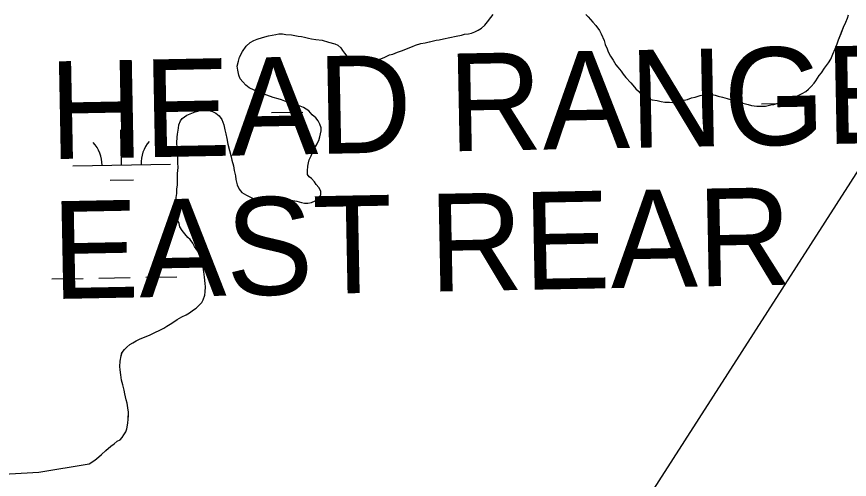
# Model space of a CAD drawing. Extents: x 3925854 to 3964121, y 224593 to 250589.
# Drawn here: x 3944344 to 3945197, y 233989 to 234463 of the extents above; entities that cross this region are included whole.
import ezdxf

# ---------------------------------------------------------------- set-up
doc = ezdxf.new("R2010")
doc.units = 0
for name, color, linetype in [('V-CHAN-NAID', 7, 'Continuous'), ('V-TOPO-SHOR', 7, 'Continuous'), ('V-UTIL-LINE', 7, 'Continuous'), ('V-WETL-SWMP', 7, 'Continuous')]:
    doc.layers.add(name, color=color, linetype=linetype)

msp = doc.modelspace()

# ---------------------------------------------------------------- linework, layer by layer
at = {"layer": 'V-TOPO-SHOR'}
for points in [[(3944653.523, 234336.388), (3944654.618, 234339.871), (3944655.36, 234343.009), (3944656.101, 234346.149), (3944655.792, 234349.3), (3944654.444, 234353.167), (3944652.736, 234356.339), (3944650.33, 234359.52), (3944646.875, 234362.715), (3944643.428, 234366.608), (3944637.878, 234370.182), (3944632.653, 234371.998), (3944627.425, 234373.469), (3944620.462, 234376.008), (3944615.237, 234377.827), (3944611.754, 234378.925), (3944606.873, 234380.387), (3944600.256, 234382.574), (3944595.728, 234384.035), (3944590.504, 234385.853), (3944587.378, 234387.643), (3944582.164, 234390.162), (3944578.703, 234393.007), (3944575.596, 234396.196), (3944572.84, 234399.382), (3944571.492, 234403.249), (3944570.507, 234408.16), (3944569.864, 234412.367), (3944571.332, 234417.593), (3944572.432, 234421.429), (3944575.309, 234427.337), (3944579.231, 234432.883), (3944583.131, 234436.68), (3944587.006, 234438.728), (3944590.522, 234440.08), (3944595.794, 234441.759), (3944602.112, 234443.427), (3944609.476, 234444.727), (3944612.634, 234445.384), (3944616.482, 234445.333), (3944619.626, 234444.942), (3944625.567, 234444.514), (3944632.545, 234443.021), (3944635.689, 234442.632), (3944638.826, 234441.888), (3944643.016, 234441.135), (3944646.156, 234440.393), (3944650.342, 234439.638), (3944656.98, 234438.849), (3944663.603, 234437.012), (3944669.876, 234435.179), (3944673.005, 234433.739), (3944676.12, 234431.249), (3944677.832, 234428.427), (3944679.895, 234425.601), (3944682.305, 234422.77), (3944684.732, 234420.989), (3944688.906, 234419.184), (3944693.094, 234418.429), (3944696.58, 234417.333), (3944700.082, 234417.636), (3944705.329, 234417.566), (3944709.886, 234418.205), (3944713.392, 234418.859), (3944716.904, 234419.862), (3944721.125, 234421.556), (3944726.055, 234423.94), (3944729.213, 234424.597), (3944734.138, 234426.631), (3944739.408, 234428.31), (3944745.035, 234430.686), (3944749.607, 234432.373), (3944752.425, 234433.735), (3944758.044, 234435.411), (3944762.605, 234436.4), (3944769.624, 234438.057), (3944773.836, 234439.05), (3944776.988, 234439.357), (3944781.199, 234440.35), (3944787.865, 234441.661), (3944794.179, 234442.978), (3944799.791, 234443.953), (3944802.953, 234444.96), (3944806.809, 234445.61), (3944809.967, 234446.267), (3944813.484, 234447.621), (3944816.656, 234449.327), (3944820.181, 234451.381), (3944823.722, 234454.482), (3944826.212, 234457.597), (3944829.769, 234462.098), (3944832.26, 234465.213)], [(3944927.074, 234465.357), (3944929.491, 234462.874), (3944931.901, 234460.044), (3944934.318, 234457.564), (3944937.418, 234454.025), (3944941.197, 234448.727), (3944942.905, 234445.554), (3944945.961, 234438.515), (3944946.958, 234434.655), (3944948.998, 234430.08), (3944950.003, 234426.918), (3944952.397, 234422.686), (3944955.14, 234418.453), (3944957.878, 234413.868), (3944959.944, 234411.392), (3944963.387, 234407.148), (3944965.449, 234404.322), (3944968.202, 234400.787), (3944973.029, 234395.475), (3944975.095, 234392.999), (3944978.192, 234389.109), (3944980.959, 234386.623), (3944983.713, 234383.439), (3944986.824, 234380.598), (3944990.306, 234379.152), (3944995.188, 234378.038), (3945000.077, 234377.272), (3945004.261, 234376.168), (3945008.099, 234375.417), (3945012.646, 234375.357), (3945016.144, 234375.31), (3945019.291, 234375.269), (3945022.793, 234375.572), (3945027.719, 234377.606), (3945031.227, 234378.259), (3945035.448, 234379.953), (3945038.954, 234380.606), (3945044.226, 234382.286), (3945047.382, 234382.943), (3945054.038, 234383.555), (3945059.625, 234382.781), (3945062.758, 234381.69), (3945066.942, 234380.586), (3945071.822, 234379.121)], [(3945071.822, 234379.121), (3945075.31, 234378.376), (3945078.79, 234376.93), (3945084.369, 234375.455), (3945087.852, 234374.36), (3945093.435, 234373.235), (3945096.919, 234372.14), (3945102.157, 234371.372), (3945105.655, 234371.325), (3945111.257, 234371.599), (3945116.522, 234372.93), (3945119.674, 234373.237), (3945124.946, 234374.919), (3945130.215, 234376.596), (3945135.14, 234378.632), (3945140.06, 234380.315), (3945143.226, 234381.671), (3945148.86, 234384.397), (3945152.387, 234386.449), (3945155.217, 234388.86), (3945158.054, 234391.622), (3945160.898, 234395.083), (3945162.68, 234397.508), (3945166.248, 234402.708), (3945168.384, 234405.479), (3945171.597, 234410.335), (3945173.733, 234413.106), (3945175.519, 234415.881), (3945178.017, 234419.696), (3945180.18, 234424.564), (3945182.353, 234430.135), (3945184.524, 234435.353), (3945185.974, 234439.181), (3945188.509, 234445.796), (3945191.047, 234452.409), (3945193.56, 234457.273), (3945195.016, 234461.453), (3945196.112, 234464.939)], [(3944536.559, 234196.243), (3944535.584, 234201.855), (3944534.95, 234206.762), (3944533.964, 234211.673), (3944532.631, 234216.588), (3944531.269, 234219.404), (3944529.565, 234222.927), (3944526.133, 234227.87), (3944524.427, 234231.041), (3944521.678, 234234.926), (3944519.258, 234237.058), (3944516.155, 234240.597), (3944513.405, 234244.132), (3944511.006, 234248.013), (3944510.349, 234251.171), (3944508.991, 234254.337), (3944507.644, 234258.203), (3944506.994, 234262.06), (3944507.05, 234266.258), (3944507.097, 234269.756), (3944507.162, 234274.653), (3944507.553, 234277.797), (3944507.959, 234281.989), (3944508.018, 234286.537), (3944508.778, 234291.076), (3944508.829, 234294.924), (3944508.872, 234298.072), (3944508.932, 234302.618), (3944509.36, 234308.56), (3944509.075, 234313.462), (3944509.145, 234318.709), (3944509.2, 234322.906), (3944508.586, 234329.212), (3944507.945, 234333.768), (3944508.375, 234339.712), (3944508.766, 234342.853), (3944509.894, 234348.786), (3944510.29, 234352.28), (3944511.746, 234356.458), (3944513.525, 234358.885), (3944518.469, 234362.318), (3944523.395, 234364.351), (3944526.911, 234365.705), (3944533.231, 234367.37), (3944536.379, 234367.329), (3944541.272, 234366.913), (3944544.755, 234365.818), (3944547.887, 234364.378), (3944551.346, 234361.531), (3944554.094, 234357.646), (3944556.124, 234352.372), (3944557.103, 234347.111), (3944558.45, 234343.245), (3944559.435, 234338.333), (3944560.406, 234332.374), (3944562.071, 234326.054), (3944563.736, 234319.733), (3944564.39, 234316.227), (3944566.061, 234310.257), (3944566.7, 234305.701), (3944568.025, 234300.085), (3944568.674, 234296.229), (3944570.003, 234290.963), (3944572.041, 234286.388), (3944574.797, 234283.201), (3944579.307, 234280.342), (3944584.173, 234277.829), (3944588.347, 234276.025), (3944592.535, 234275.269), (3944595.675, 234274.53), (3944602.325, 234274.79), (3944606.527, 234275.085), (3944610.386, 234275.732), (3944614.586, 234276.027), (3944618.788, 234276.322), (3944622.628, 234275.57), (3944626.817, 234274.815), (3944631.005, 234274.061), (3944635.887, 234272.947), (3944639.027, 234272.206), (3944642.175, 234272.163), (3944646.031, 234272.812), (3944649.904, 234274.51), (3944653.432, 234276.912), (3944655.583, 234280.731), (3944655.634, 234284.58), (3944653.582, 234288.104), (3944650.825, 234291.291), (3944649.113, 234294.113), (3944646.006, 234297.302), (3944643.582, 234299.083), (3944641.865, 234301.555), (3944641.917, 234305.404), (3944642.326, 234309.946), (3944643.072, 234313.434), (3944643.813, 234316.573), (3944645.617, 234320.747), (3944647.417, 234324.573), (3944649.93, 234329.437), (3944651.726, 234332.912), (3944653.523, 234336.388)], [(3944418.42, 234005.37), (3944424.069, 234009.144), (3944428.312, 234012.585), (3944430.794, 234015.001), (3944435.396, 234019.138), (3944440.35, 234023.271), (3944443.883, 234025.929), (3944447.068, 234028.594), (3944450.035, 234029.808), (3944452.167, 234032.229), (3944453.953, 234035.004), (3944455.745, 234038.129), (3944456.837, 234041.265), (3944457.959, 234046.848), (3944458.365, 234051.04), (3944458.412, 234054.538), (3944458.463, 234058.384), (3944457.818, 234062.593), (3944457.185, 234067.5), (3944456.181, 234071.01), (3944454.86, 234076.976), (3944454.211, 234080.832), (3944452.882, 234086.098), (3944451.549, 234091.015), (3944450.568, 234096.274), (3944449.937, 234101.531), (3944449.634, 234105.033), (3944450.054, 234110.276), (3944451.176, 234115.859), (3944451.924, 234119.349), (3944454.414, 234122.464), (3944456.894, 234124.879), (3944460.081, 234127.635), (3944462.903, 234129.347), (3944466.428, 234131.399), (3944470.653, 234133.443), (3944476.633, 234135.813), (3944480.854, 234137.507), (3944486.137, 234140.234), (3944490.008, 234141.932), (3944494.938, 234144.316), (3944497.764, 234146.378), (3944503.052, 234149.457), (3944508.35, 234153.235), (3944513.286, 234155.969), (3944517.511, 234158.011), (3944521.035, 234160.065), (3944525.271, 234162.808), (3944527.743, 234164.524), (3944531.288, 234167.975), (3944533.768, 234170.391), (3944535.203, 234173.17), (3944536.668, 234178.051), (3944537.063, 234181.543), (3944537.479, 234186.435), (3944537.176, 234189.939), (3944536.559, 234196.243)], [(3944288.589, 233992.492), (3944366.559, 233996.907), (3944418.42, 234005.37)]]:
    msp.add_lwpolyline(points, dxfattribs=at)
at = {"layer": 'V-UTIL-LINE'}
msp.add_lwpolyline([(3951084.343, 243921.319), (3947981.77, 238738.296), (3948844.302, 237642.921), (3949260.796, 236134.673), (3945931.135, 235655.081), (3945509.058, 234777.685), (3942603.575, 230254.808)], dxfattribs=at)
at = {"layer": 'V-WETL-SWMP'}
for p, q in [((3945106.951, 234373.981), (3945122.916, 234374.271)), ((3944605.126, 234364.856), (3944637.121, 234365.438)), ((3944451.482, 234311.312), (3944450.828, 234347.306)), ((3944401.49, 234310.403), (3944501.474, 234312.221)), ((3944439.765, 234295.665), (3944463.761, 234296.101)), ((3944428.177, 234195.437), (3944460.171, 234196.019)), ((3944476.169, 234196.31), (3944508.164, 234196.891)), ((3944380.185, 234194.564), (3944412.179, 234195.146))]:
    msp.add_line(p, q, dxfattribs=at)
for points in [[(3944676.121, 234431.249), (3944677.833, 234428.427), (3944679.895, 234425.601), (3944682.306, 234422.77), (3944684.732, 234420.989), (3944688.906, 234419.184), (3944693.095, 234418.429), (3944696.579, 234417.333), (3944700.081, 234417.637), (3944705.328, 234417.567), (3944709.885, 234418.206), (3944713.392, 234418.859), (3944716.904, 234419.862), (3944721.125, 234421.556), (3944726.054, 234423.939), (3944729.212, 234424.597), (3944734.137, 234426.631), (3944739.407, 234428.311), (3944745.036, 234430.685), (3944749.607, 234432.374), (3944752.424, 234433.736), (3944758.044, 234435.411), (3944762.605, 234436.4), (3944773.836, 234439.05), (3944776.989, 234439.358), (3944781.2, 234440.351), (3944787.865, 234441.662), (3944794.18, 234442.978), (3944799.791, 234443.953), (3944802.953, 234444.961), (3944806.81, 234445.61), (3944809.967, 234446.267), (3944813.484, 234447.62), (3944816.655, 234449.327), (3944820.181, 234451.38), (3944823.721, 234454.482), (3944826.211, 234457.597), (3944829.769, 234462.098), (3944832.26, 234465.214)], [(3944927.074, 234465.356), (3944929.49, 234462.875), (3944931.901, 234460.044), (3944934.317, 234457.563)], [(3944934.317, 234457.563), (3944937.419, 234454.024), (3944941.197, 234448.726), (3944942.905, 234445.554), (3944945.96, 234438.516), (3944946.958, 234434.655), (3944948.997, 234430.08), (3944950.004, 234426.917), (3944952.397, 234422.687), (3944955.14, 234418.453), (3944957.878, 234413.868), (3944959.945, 234411.392), (3944963.387, 234407.148), (3944965.449, 234404.322), (3944968.201, 234400.787), (3944973.028, 234395.475), (3944975.095, 234392.998), (3944978.192, 234389.109), (3944980.958, 234386.623), (3944983.714, 234383.438), (3944986.825, 234380.598), (3944990.305, 234379.152), (3944995.188, 234378.038), (3945000.076, 234377.273), (3945004.26, 234376.168), (3945008.098, 234375.417), (3945019.292, 234375.269), (3945022.794, 234375.572), (3945027.719, 234377.606), (3945031.227, 234378.259), (3945035.447, 234379.953), (3945038.955, 234380.606), (3945044.225, 234382.285), (3945047.382, 234382.943), (3945054.038, 234383.555), (3945059.625, 234382.781), (3945062.759, 234381.69), (3945066.943, 234380.585), (3945071.822, 234379.121), (3945075.31, 234378.375), (3945078.79, 234376.929), (3945084.368, 234375.456), (3945087.852, 234374.36), (3945093.435, 234373.236), (3945096.919, 234372.14), (3945102.157, 234371.371), (3945105.655, 234371.325), (3945111.256, 234371.6), (3945116.522, 234372.93), (3945119.675, 234373.238), (3945130.215, 234376.597), (3945135.14, 234378.631), (3945140.06, 234380.315), (3945143.227, 234381.672), (3945148.861, 234384.396), (3945152.387, 234386.449), (3945155.218, 234388.86), (3945158.053, 234391.622), (3945160.898, 234395.083), (3945162.679, 234397.508), (3945166.247, 234402.709), (3945168.383, 234405.479), (3945171.596, 234410.335), (3945173.732, 234413.105), (3945175.518, 234415.88), (3945178.018, 234419.696), (3945180.181, 234424.565), (3945182.354, 234430.134), (3945184.523, 234435.353), (3945185.973, 234439.182), (3945191.046, 234452.41), (3945193.56, 234457.274), (3945195.015, 234461.453), (3945196.111, 234464.938)], [(3944544.756, 234365.818), (3944547.886, 234364.377), (3944551.346, 234361.532), (3944554.094, 234357.647), (3944556.123, 234352.372), (3944557.103, 234347.111), (3944558.451, 234343.245), (3944559.435, 234338.334), (3944560.406, 234332.373), (3944563.737, 234319.734), (3944564.39, 234316.227), (3944566.06, 234310.257), (3944566.7, 234305.701), (3944568.025, 234300.085), (3944568.673, 234296.228), (3944570.003, 234290.963), (3944572.041, 234286.387), (3944574.798, 234283.202), (3944579.308, 234280.343), (3944584.173, 234277.83), (3944588.347, 234276.025), (3944592.536, 234275.27), (3944595.675, 234274.529), (3944602.325, 234274.79), (3944606.528, 234275.085), (3944610.385, 234275.733), (3944618.789, 234276.321), (3944622.628, 234275.571), (3944631.004, 234274.06), (3944635.887, 234272.946), (3944639.026, 234272.205), (3944642.175, 234272.163), (3944646.032, 234272.811), (3944649.903, 234274.509), (3944653.433, 234276.912), (3944655.583, 234280.732), (3944655.634, 234284.579), (3944653.582, 234288.105), (3944650.825, 234291.29), (3944649.113, 234294.112), (3944646.007, 234297.302), (3944643.581, 234299.083), (3944641.865, 234301.555), (3944641.916, 234305.403), (3944642.326, 234309.946), (3944643.072, 234313.434), (3944643.813, 234316.573), (3944645.618, 234320.748), (3944647.418, 234324.572), (3944653.522, 234336.387), (3944654.618, 234339.871), (3944656.1, 234346.149), (3944655.792, 234349.301), (3944654.444, 234353.168), (3944652.737, 234356.339), (3944650.33, 234359.52), (3944646.874, 234362.714), (3944643.427, 234366.608), (3944637.877, 234370.181), (3944632.653, 234371.999), (3944627.424, 234373.468), (3944620.461, 234376.009), (3944615.237, 234377.828), (3944611.753, 234378.924), (3944606.874, 234380.388), (3944600.256, 234382.575), (3944595.727, 234384.034), (3944590.503, 234385.853), (3944587.378, 234387.644), (3944582.164, 234390.162), (3944578.703, 234393.006), (3944575.597, 234396.196), (3944572.84, 234399.382), (3944571.492, 234403.248), (3944570.507, 234408.159), (3944569.863, 234412.366), (3944571.332, 234417.594), (3944572.433, 234421.428), (3944575.31, 234427.338), (3944579.232, 234432.884), (3944583.131, 234436.68), (3944587.006, 234438.728), (3944590.523, 234440.081), (3944595.793, 234441.76), (3944602.112, 234443.426), (3944609.477, 234444.728), (3944612.634, 234445.385), (3944616.482, 234445.334), (3944619.626, 234444.943), (3944625.568, 234444.514), (3944632.545, 234443.022), (3944635.689, 234442.631), (3944638.827, 234441.889), (3944643.016, 234441.134), (3944646.155, 234440.393), (3944650.343, 234439.638), (3944656.98, 234438.85), (3944663.603, 234437.013), (3944669.876, 234435.18), (3944673.006, 234433.739), (3944676.121, 234431.249)], [(3944288.589, 233992.492), (3944366.558, 233996.907), (3944418.421, 234005.369), (3944424.069, 234009.143), (3944428.313, 234012.585), (3944430.794, 234015.001), (3944435.397, 234019.138), (3944440.35, 234023.271), (3944443.883, 234025.93), (3944447.067, 234028.593), (3944450.036, 234029.808), (3944452.168, 234032.229), (3944453.954, 234035.004), (3944455.745, 234038.129), (3944456.836, 234041.264), (3944457.959, 234046.847), (3944458.365, 234051.039), (3944458.462, 234058.385), (3944457.818, 234062.592), (3944457.184, 234067.499), (3944456.181, 234071.01), (3944454.86, 234076.976), (3944454.212, 234080.833), (3944452.882, 234086.098), (3944451.548, 234091.014), (3944450.568, 234096.275), (3944449.938, 234101.531), (3944449.634, 234105.034), (3944450.054, 234110.276), (3944451.177, 234115.859), (3944451.923, 234119.348), (3944454.414, 234122.463), (3944456.895, 234124.879), (3944460.08, 234127.636), (3944462.902, 234129.348), (3944466.428, 234131.4), (3944470.653, 234133.444), (3944476.632, 234135.813), (3944480.853, 234137.507), (3944486.137, 234140.235), (3944490.008, 234141.933), (3944494.937, 234144.317), (3944497.764, 234146.379), (3944503.052, 234149.457), (3944508.35, 234153.236), (3944513.285, 234155.969), (3944517.51, 234158.012), (3944521.036, 234160.065), (3944525.271, 234162.807), (3944527.742, 234164.524), (3944533.768, 234170.392), (3944535.204, 234173.171), (3944536.668, 234178.05), (3944537.064, 234181.543), (3944537.479, 234186.436), (3944537.176, 234189.939), (3944536.56, 234196.244), (3944535.585, 234201.855), (3944534.95, 234206.761), (3944533.965, 234211.672), (3944532.631, 234216.588), (3944529.566, 234222.926), (3944526.133, 234227.87), (3944524.426, 234231.041), (3944521.679, 234234.926), (3944519.258, 234237.057), (3944516.156, 234240.597), (3944513.404, 234244.132), (3944511.007, 234248.012), (3944510.349, 234251.17), (3944508.991, 234254.337), (3944507.643, 234258.203), (3944506.995, 234262.06), (3944507.162, 234274.653), (3944507.553, 234277.796), (3944507.959, 234281.989), (3944508.019, 234286.537), (3944508.779, 234291.075), (3944508.932, 234302.618), (3944509.36, 234308.56), (3944509.076, 234313.462), (3944509.201, 234322.906), (3944508.585, 234329.212), (3944507.945, 234333.769), (3944508.374, 234339.711), (3944508.766, 234342.854), (3944509.894, 234348.787), (3944510.29, 234352.28), (3944511.745, 234356.459), (3944513.526, 234358.885), (3944518.47, 234362.318), (3944523.395, 234364.352), (3944526.912, 234365.704), (3944533.231, 234367.37), (3944536.379, 234367.328), (3944541.272, 234366.913), (3944544.756, 234365.818)]]:
    msp.add_lwpolyline(points, dxfattribs=at)
for centre, start, end in [((3944396.24, 234310.782), 0.269879, 41.813537), ((3944506.707, 234312.791), 140.269876, 181.813534)]:
    msp.add_arc(centre, 35.246, start, end, dxfattribs=at)

# ---------------------------------------------------------------- texts
at = {"layer": 'V-CHAN-NAID'}
for s, p in [('HEAD RANGE', (3944378.264, 234317.148)), ('EAST REAR', (3944380.867, 234173.986))]:
    msp.add_text(s, height=100, rotation=1.11601, dxfattribs=at).set_placement(p)

doc.saveas('drawing.dxf')
